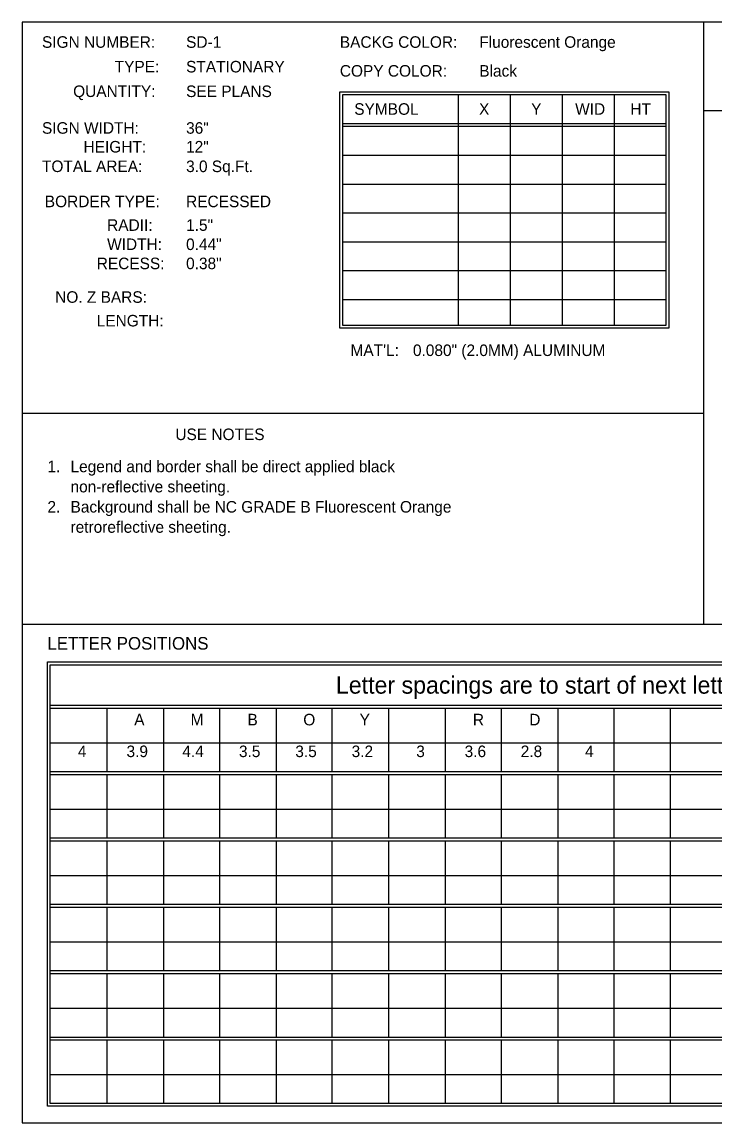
# Model space of a CAD drawing. Extents: x 57.2 to 85.4, y 153.3 to 173.4.
# Drawn here: x 57.21 to 63.11, y 163.71 to 173.1 of the extents above; entities that cross this region are included whole.
import ezdxf

# ---------------------------------------------------------------- set-up
doc = ezdxf.new("R2010")
doc.units = 0
doc.layers.add('Default', color=7, linetype='Continuous')

msp = doc.modelspace()

# ---------------------------------------------------------------- linework, layer by layer
at = {"layer": 'Default'}
for p, q in [((69.7108, 173.0983), (57.2061, 173.0983)), ((57.2061, 173.0983), (57.2061, 163.7124)), ((63.0173, 167.9646), (63.0173, 173.0983)), ((59.9146, 172.5043), (62.7186, 172.5043)), ((59.9146, 170.4874), (59.9146, 172.5043)), ((59.9392, 172.4797), (62.694, 172.4797)), ((59.9392, 170.512), (59.9392, 172.4797)), ((60.9231, 172.4797), (60.9231, 170.512)), ((61.3658, 172.4797), (61.3658, 170.512)), ((61.8085, 172.4797), (61.8085, 170.512)), ((62.2513, 172.4797), (62.2513, 170.512)), ((62.694, 172.4797), (62.694, 170.512)), ((62.7186, 172.5043), (62.7186, 170.4874)), ((63.0173, 172.3449), (69.7108, 172.3449)), ((59.9392, 172.2337), (62.694, 172.2337)), ((59.9392, 172.2091), (62.694, 172.2091)), ((59.9392, 171.9631), (62.694, 171.9631)), ((59.9392, 171.7172), (62.694, 171.7172)), ((59.9392, 171.4712), (62.694, 171.4712)), ((59.9392, 171.2253), (62.694, 171.2253)), ((59.9392, 170.9793), (62.694, 170.9793)), ((59.9392, 170.7333), (62.694, 170.7333)), ((62.7186, 170.4874), (59.9146, 170.4874)), ((62.694, 170.512), (59.9392, 170.512)), ((57.2061, 169.7625), (63.0173, 169.7625)), ((57.2061, 167.9646), (69.7108, 167.9646)), ((57.4225, 167.6428), (69.4747, 167.6428)), ((57.4225, 163.855), (57.4225, 167.6428)), ((57.4471, 167.6182), (69.4501, 167.6182)), ((57.4471, 163.8796), (57.4471, 167.6182)), ((57.4471, 167.2739), (69.4501, 167.2739)), ((57.4471, 167.2493), (69.4501, 167.2493)), ((57.9292, 167.2493), (57.9292, 166.7082)), ((58.4113, 167.2493), (58.4113, 166.7082)), ((58.8885, 167.2493), (58.8885, 166.7082)), ((59.3706, 167.2493), (59.3706, 166.7082)), ((59.8477, 167.2493), (59.8477, 166.7082)), ((60.3298, 167.2493), (60.3298, 166.7082)), ((60.8119, 167.2493), (60.8119, 166.7082)), ((61.2891, 167.2493), (61.2891, 166.7082)), ((61.7712, 167.2493), (61.7712, 166.7082)), ((62.2483, 167.2493), (62.2483, 166.7082)), ((62.7304, 167.2493), (62.7304, 166.7082)), ((57.4471, 166.9541), (68.0137, 166.9541)), ((57.4471, 166.7082), (69.4501, 166.7082)), ((57.4471, 166.6836), (69.4501, 166.6836)), ((57.9292, 166.6836), (57.9292, 166.1425)), ((58.4113, 166.6836), (58.4113, 166.1425)), ((58.8885, 166.6836), (58.8885, 166.1425)), ((59.3706, 166.6836), (59.3706, 166.1425)), ((59.8477, 166.6836), (59.8477, 166.1425)), ((60.3298, 166.6836), (60.3298, 166.1425)), ((60.8119, 166.6836), (60.8119, 166.1425)), ((61.2891, 166.6836), (61.2891, 166.1425)), ((61.7712, 166.6836), (61.7712, 166.1425)), ((62.2483, 166.6836), (62.2483, 166.1425)), ((62.7304, 166.6836), (62.7304, 166.1425)), ((57.4471, 166.3884), (68.0137, 166.3884)), ((57.4471, 166.1425), (69.4501, 166.1425)), ((57.4471, 166.1179), (69.4501, 166.1179)), ((57.9292, 166.1179), (57.9292, 165.5768)), ((58.4113, 166.1179), (58.4113, 165.5768)), ((58.8885, 166.1179), (58.8885, 165.5768)), ((59.3706, 166.1179), (59.3706, 165.5768)), ((59.8477, 166.1179), (59.8477, 165.5768)), ((60.3298, 166.1179), (60.3298, 165.5768)), ((60.8119, 166.1179), (60.8119, 165.5768)), ((61.2891, 166.1179), (61.2891, 165.5768)), ((61.7712, 166.1179), (61.7712, 165.5768)), ((62.2483, 166.1179), (62.2483, 165.5768)), ((62.7304, 166.1179), (62.7304, 165.5768)), ((57.4471, 165.8227), (68.0137, 165.8227)), ((57.4471, 165.5768), (69.4501, 165.5768)), ((57.4471, 165.5522), (69.4501, 165.5522)), ((57.9292, 165.5522), (57.9292, 165.011)), ((58.4113, 165.5522), (58.4113, 165.011)), ((58.8885, 165.5522), (58.8885, 165.011)), ((59.3706, 165.5522), (59.3706, 165.011)), ((59.8477, 165.5522), (59.8477, 165.011)), ((60.3298, 165.5522), (60.3298, 165.011)), ((60.8119, 165.5522), (60.8119, 165.011)), ((61.2891, 165.5522), (61.2891, 165.011)), ((61.7712, 165.5522), (61.7712, 165.011)), ((62.2483, 165.5522), (62.2483, 165.011)), ((62.7304, 165.5522), (62.7304, 165.011)), ((57.4471, 165.257), (68.0137, 165.257)), ((57.4471, 165.011), (69.4501, 165.011)), ((57.4471, 164.9864), (69.4501, 164.9864)), ((57.9292, 164.9864), (57.9292, 164.4453)), ((57.9292, 164.9864), (57.9292, 164.4453)), ((58.4113, 164.9864), (58.4113, 164.4453)), ((58.4113, 164.9864), (58.4113, 164.4453)), ((58.8885, 164.9864), (58.8885, 164.4453)), ((58.8885, 164.9864), (58.8885, 164.4453)), ((59.3706, 164.9864), (59.3706, 164.4453)), ((59.3706, 164.9864), (59.3706, 164.4453)), ((59.8477, 164.9864), (59.8477, 164.4453)), ((59.8477, 164.9864), (59.8477, 164.4453)), ((60.3298, 164.9864), (60.3298, 164.4453)), ((60.3298, 164.9864), (60.3298, 164.4453)), ((60.8119, 164.9864), (60.8119, 164.4453)), ((60.8119, 164.9864), (60.8119, 164.4453)), ((61.2891, 164.9864), (61.2891, 164.4453)), ((61.2891, 164.9864), (61.2891, 164.4453)), ((61.7712, 164.9864), (61.7712, 164.4453)), ((61.7712, 164.9864), (61.7712, 164.4453)), ((62.2483, 164.9864), (62.2483, 164.4453)), ((62.2483, 164.9864), (62.2483, 164.4453)), ((62.7304, 164.9864), (62.7304, 164.4453)), ((62.7304, 164.9864), (62.7304, 164.4453)), ((57.4471, 164.6913), (68.0137, 164.6913)), ((57.4471, 164.4453), (69.4501, 164.4453)), ((57.4471, 164.4207), (69.4501, 164.4207)), ((57.9292, 164.4207), (57.9292, 163.8796)), ((58.4113, 164.4207), (58.4113, 163.8796)), ((58.8885, 164.4207), (58.8885, 163.8796)), ((59.3706, 164.4207), (59.3706, 163.8796)), ((59.8477, 164.4207), (59.8477, 163.8796)), ((60.3298, 164.4207), (60.3298, 163.8796)), ((60.8119, 164.4207), (60.8119, 163.8796)), ((61.2891, 164.4207), (61.2891, 163.8796)), ((61.7712, 164.4207), (61.7712, 163.8796)), ((62.2483, 164.4207), (62.2483, 163.8796)), ((62.7304, 164.4207), (62.7304, 163.8796)), ((57.4471, 164.1256), (68.0137, 164.1256)), ((57.4471, 164.1256), (68.0137, 164.1256)), ((69.4501, 163.8796), (57.4471, 163.8796)), ((69.4747, 163.855), (57.4225, 163.855)), ((57.2061, 163.7124), (69.7108, 163.7124))]:
    msp.add_line(p, q, dxfattribs=at)

# ---------------------------------------------------------------- texts
for s, height, p in [('SIGN NUMBER:', 0.098375, (57.3762, 172.8786)), ('SD-1', 0.09837, (58.6043, 172.8784)), ('BACKG COLOR:', 0.098375, (59.9146, 172.8784)), ('Fluorescent Orange', 0.098375, (61.103, 172.8784)), ('TYPE:', 0.09838, (57.996, 172.6687)), ('STATIONARY', 0.09837, (58.6043, 172.6685)), ('COPY COLOR:', 0.098375, (59.9146, 172.6327)), ('Black', 0.09837, (61.103, 172.6327)), ('QUANTITY:', 0.09838, (57.6418, 172.4589)), ('SEE PLANS', 0.09837, (58.6043, 172.4587)), ('SYMBOL', 0.09838, (60.0376, 172.3075)), ('X', 0.0984, (61.1009, 172.3075)), ('Y', 0.0984, (61.5451, 172.3075)), ('WID', 0.09838, (61.9201, 172.3075)), ('HT', 0.09838, (62.3904, 172.3075)), ('SIGN WIDTH:', 0.098375, (57.3762, 172.146)), ('36"', 0.09837, (58.6043, 172.1459)), ('HEIGHT:', 0.09838, (57.7304, 171.9859)), ('12"', 0.09837, (58.6043, 171.9858)), ('TOTAL AREA:', 0.098375, (57.3762, 171.8191)), ('3.0 Sq.Ft.', 0.09837, (58.6043, 171.8189)), ('BORDER TYPE:', 0.098375, (57.4001, 171.5197)), ('RECESSED', 0.09837, (58.6043, 171.5195)), ('RADII:', 0.09838, (57.9313, 171.3181)), ('1.5"', 0.09837, (58.6043, 171.3181)), ('WIDTH:', 0.09838, (57.9313, 171.1546)), ('0.44"', 0.09837, (58.6043, 171.1545)), ('RECESS:', 0.09838, (57.8427, 170.9912)), ('0.38"', 0.09837, (58.6043, 170.9912)), ('NO. Z BARS:', 0.098375, (57.4886, 170.7046)), ('LENGTH:', 0.09838, (57.8427, 170.503)), ("MAT'L:", 0.09838, (60.0056, 170.2508)), ('0.080" (2.0MM) ALUMINUM', 0.098375, (60.5377, 170.2508)), ('USE NOTES', 0.09838, (58.5129, 169.5342)), ('1.', 0.09838, (57.4225, 169.2605)), ('Legend and border shall be direct applied black', 0.098375, (57.6193, 169.2605)), ('non-reflective sheeting.', 0.098375, (57.6193, 169.0884)), ('2.', 0.09838, (57.4225, 168.9162)), ('Background shall be NC GRADE B Fluorescent Orange', 0.098375, (57.6193, 168.9162)), ('retroreflective sheeting.', 0.098375, (57.6193, 168.7441)), ('LETTER POSITIONS', 0.107428, (57.4225, 167.7478)), ('Letter spacings are to start of next letter', 0.147548, (59.8813, 167.3723)), ('A', 0.0984, (58.1622, 167.1021)), ('M', 0.0984, (58.6425, 167.1021)), ('B', 0.0984, (59.1275, 167.1021)), ('O', 0.0984, (59.603, 167.1021)), ('Y', 0.0984, (60.0833, 167.1021)), ('R', 0.0984, (61.0485, 167.1021)), ('D', 0.0984, (61.5288, 167.1021)), ('4', 0.0984, (57.6819, 166.8315)), ('3.9', 0.09837, (58.0966, 166.8315)), ('4.4', 0.09837, (58.5722, 166.8315)), ('3.5', 0.09837, (59.0548, 166.8315)), ('3.5', 0.09837, (59.535, 166.8315)), ('3.2', 0.09837, (60.0153, 166.8315)), ('3', 0.0984, (60.5659, 166.8315)), ('3.6', 0.09837, (60.9782, 166.8315)), ('2.8', 0.09837, (61.4561, 166.8315)), ('4', 0.0984, (62.0043, 166.8315))]:
    msp.add_text(s, height=height, dxfattribs=at).set_placement(p)

doc.saveas('drawing.dxf')
